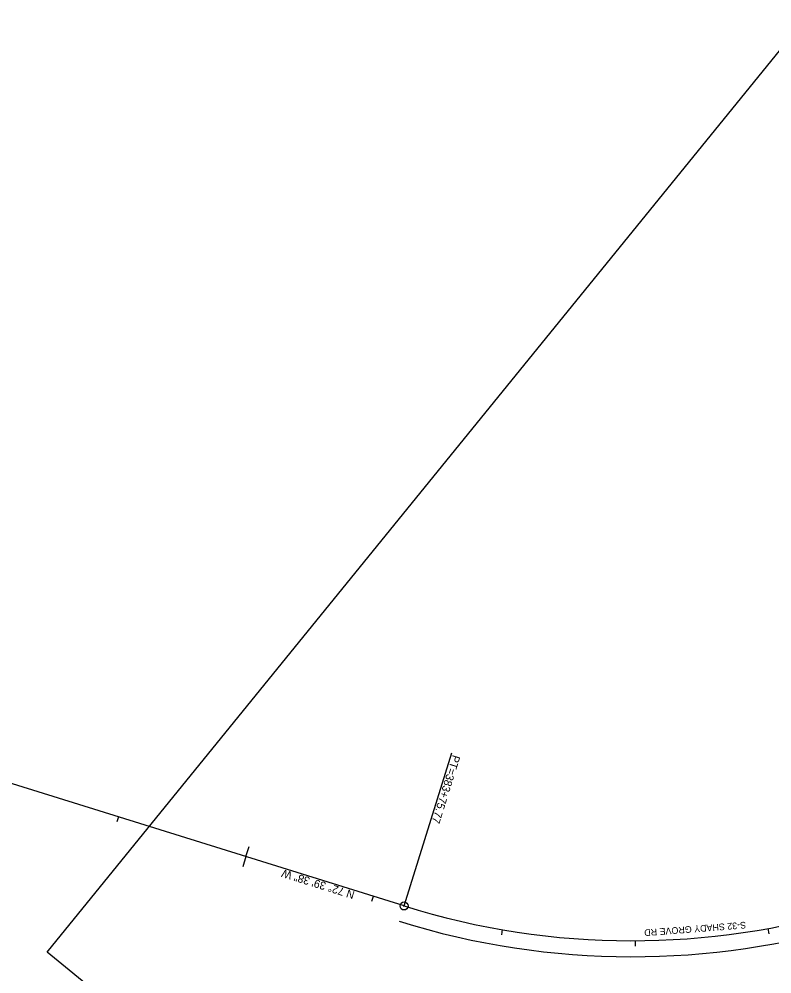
# Model space of a CAD drawing. Extents: x 144 to 1452322, y 4017 to 1128039.
# Drawn here: x 1449745 to 1450309, y 1126625 to 1127341 of the extents above; entities that cross this region are included whole.
import ezdxf

# ---------------------------------------------------------------- set-up
doc = ezdxf.new("R2010")
doc.units = 0
for name, color, linetype in [('RD_EX_Road Text', 7, 'Continuous'), ('RD_HC_Cl', 7, 'Continuous'), ('RD_HC_Data', 7, 'Continuous'), ('RD_HC_Data_Tic', 7, 'Continuous'), ('RD_SHT_ShtClip', 7, 'Continuous'), ('RD_Sketch8', 7, 'Continuous'), ('RD_SMD_Locator', 7, 'Continuous')]:
    doc.layers.add(name, color=color, linetype=linetype)

msp = doc.modelspace()

# ---------------------------------------------------------------- linework, layer by layer
at = {"layer": 'RD_HC_Cl'}
msp.add_line((1450033.34, 1126676.03), (1449295.29, 1126906.46), dxfattribs=at)
msp.add_arc((1450204.11, 1127222.95), 572.96, 252.66042, 320.91666, dxfattribs=at)
at = {"layer": 'RD_HC_Data'}
msp.add_line((1450033.34, 1126676.03), (1450069.22, 1126790.92), dxfattribs=at)
for radius in [3, 0.282]:
    msp.add_circle((1450033.34, 1126676.03), radius, dxfattribs=at)
at = {"layer": 'RD_HC_Data_Tic'}
for p, q in [((1449819.31, 1126742.85), (1449818.11, 1126739.04)), ((1449914.76, 1126713.05), (1449917.15, 1126720.69)), ((1449914.76, 1126713.05), (1449912.38, 1126705.41)), ((1450010.22, 1126683.25), (1450009.03, 1126679.43)), ((1450106.95, 1126658.29), (1450106.28, 1126654.34)), ((1450305.94, 1126659.11), (1450306.65, 1126655.17)), ((1450206.48, 1126649.99), (1450206.5, 1126645.99))]:
    msp.add_line(p, q, dxfattribs=at)
at = {"layer": 'RD_SHT_ShtClip'}
for p, q in [((1449765.76, 1126641.3), (1450900.57, 1128038.52)), ((1450619.61, 1125947.81), (1449765.76, 1126641.3))]:
    msp.add_line(p, q, dxfattribs=at)
at = {"layer": 'RD_Sketch8'}
msp.add_arc((1450204.11, 1127222.95), 584.96, 252.66042, 320.91666, dxfattribs=at)
at = {"layer": 'RD_SMD_Locator'}
msp.add_circle((1450033.34, 1126676.03), 0.15, dxfattribs=at)

# ---------------------------------------------------------------- texts
at = {"layer": 'RD_EX_Road Text'}
msp.add_text('S-32 SHADY GROVE RD', height=5, rotation=184.4336, dxfattribs=at).set_placement((1450289.49, 1126664.28))
at = {"layer": 'RD_HC_Data'}
for s, rotation, p in [('PT=383+75.77', 252.66042, (1450069.83, 1126789.69)), ('N 72%%d 39\' 38" W', 162.66042, (1449996.8, 1126686.83))]:
    msp.add_text(s, height=6, rotation=rotation, dxfattribs=at).set_placement(p)

doc.saveas('drawing.dxf')
